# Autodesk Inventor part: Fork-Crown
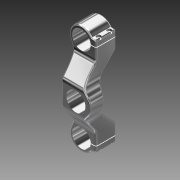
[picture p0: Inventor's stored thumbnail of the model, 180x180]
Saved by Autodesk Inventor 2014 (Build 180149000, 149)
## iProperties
Shininess: 64.0
Length Units: 11272
Angle Units: 11279
Time Units: 11290
Mass Units: 11286
Length Display Precision: 3
Angle Display Precision: 2
Compacted: True
Created: 2001-11
Part Number: Fork-Crown
Document SubType Name: Modeling
Designer: Autodesk, Inc.
Mass: 96.1049 g
Surface Area: 286.05 cm^2
Volume: 96.1049 cm^3
Density: 1 g/cm^3
Material: Generic
Appearance: Chrome - Polished
Density: 0.0
Volumn: 0.0
Area: 0.0
PropertySet Name: Model Information
Control State: 0
Master: False
Checked Out: False
Author: Autodesk, Inc.
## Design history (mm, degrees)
sketch "Sketch1"
  geometry: L1 (387.107, 198.738)-(394.972, 198.738); L2 (387.081, 199.805)-(394.972, 199.805); L3 (394.972, 205.703)-(394.972, 199.805); L4 (390.064, 208.878)-(391.797, 208.878); L5 (362.993, 135.224)-(362.993, 160.563); L6 (394.972, 198.738)-(394.972, 166.433); L7 (362.993, 135.224)-(406.863, 135.224); L8 (362.993, 135.224)-(362.993, 109.884); L9 (387.081, 70.642)-(394.972, 70.642); L10 (394.972, 64.744)-(394.972, 70.642); L11 (390.064, 61.569)-(391.797, 61.569); L12 (387.107, 71.709)-(394.972, 71.709); L13 (394.972, 71.709)-(394.972, 104.014); A1 r 13.97 centre (373.138, 198.936) between (387.081, 199.805) and (387.107, 198.738); A2 r 3.175 centre (391.797, 205.703) between (394.972, 205.703) and (391.797, 208.878); A3 r 3.048 centre (390.064, 211.926) between (387.646, 210.07) and (390.064, 208.878); A4 r 18.288 centre (373.138, 198.936) between (387.646, 210.07) and (356.426, 191.509); A5 r 76.2 centre (286.793, 160.563) between (362.993, 160.563) and (356.426, 191.509); A6 r 25.4 centre (420.372, 166.433) between (394.972, 166.433) and (401.412, 149.532); A7 r 21.504 centre (385.359, 135.224) between (406.863, 135.224) and (401.412, 149.532); A8 r 76.2 centre (286.793, 109.884) between (356.426, 78.938) and (362.993, 109.884); A9 r 18.288 centre (373.138, 71.511) between (356.426, 78.938) and (387.646, 60.377); A10 r 3.175 centre (391.797, 64.744) between (391.797, 61.569) and (394.972, 64.744); A11 r 3.048 centre (390.064, 58.521) between (390.064, 61.569) and (387.646, 60.377); A12 r 13.97 centre (373.138, 71.511) between (387.107, 71.709) and (387.081, 70.642); A13 r 25.4 centre (420.372, 104.014) between (401.412, 120.915) and (394.972, 104.014); A14 r 21.504 centre (385.359, 135.224) between (401.412, 120.915) and (406.863, 135.224)
  constraints: 28 point on circle, 26 end point, 18 symmetric about line, 14 centre point, 8 tangent, 3 horizontal, 3 vertical, 1 collinear, 1 concentric, 1 horizontal alignment, 1 perpendicular, 15 other
  dimensions: "d1" = 13.97 radius of A1; "d7" = 76.2 radius of A5; "d9" = 18.288 radius of A4; "d92" = 3.175 radius of A2; "d94" = 5.89767 distance from line of A2.centre L2; "d95" = 1.06735 distance between parallel lines of L2 L1; "d99" = 12.2212 horizontal distance of A7.centre A1.centre; "d100" = 25.4 radius of A6; "d101" = 21.50376 radius of A7; "d102" = 3.048 radius of A3; "d103" = 25.33944 distance of L5.start L5.end; "d104" = 43.87007 distance of L5.start L7.end
extrude "ExtrusionBlind1" new body sketch "Sketch1" distance "d16" = 76.2; taper "d17" = 0 deg
node "WorkPlane1"
workaxis "Work Axis4"
sketch "Sketch9"
  geometry: L1 (28.214, 35.429)-(47.471, 16.806); L2 (47.471, 16.806)-(82.009, 16.806); L3 (82.009, 47.286)-(45.305, 47.286); L4 (45.305, 47.286)-(19.099, 67.761); L5 (19.099, 67.761)-(0.009, 67.761); L6 (0.009, 45.941)-(0.009, 67.761); L7 (0.009, -15.24)-(0.009, 91.44) reference; L8 (25.348, 76.2)-(-25.331, 76.2) reference; L9 (82.009, 0)-(82.009, 76.2) reference; L10 (-25.331, 0)-(25.348, 0) reference; L11 (-28.197, 35.429)-(-47.454, 16.806); L12 (-45.288, 47.286)-(-19.081, 67.761); L13 (-19.081, 67.761)-(0.009, 67.761); L14 (0.009, 45.941)-(0.009, 67.761); L15 (-81.992, 47.286)-(-45.288, 47.286); L16 (-47.454, 16.806)-(-81.992, 16.806); L17 (-81.992, 0)-(-81.992, 76.2) reference; A1 r 37.592 centre (2.081, 8.406) between (28.214, 35.429) and (0.009, 45.941); A2 r 37.592 centre (-2.064, 8.406) between (0.009, 45.941) and (-28.197, 35.429)
  constraints: 24 end point, 5 point on line, 5 symmetric about line, 4 point on circle, 3 horizontal, 2 centre point, 1 tangent, 1 vertical, 7 other
  dimensions: "d26" = 30.48 vertical distance of L1.end L3.end; "d30" = 37.592 radius of A1; "d105" = 8.43916 distance between parallel lines of L5 L8; "d106" = 8.40601 distance from line of L10 A1.centre; "d108" = 142 deg angle of L4 L5; "d109" = 19.09001 distance of L4.end L5.end; "d110" = 20.47486 distance between parallel lines of L5 L3; "d111" = 135.959 deg angle of L2 L1
extrude "ExtrusionThru1" sketch "Sketch9" stored distance "d35" = 3.302; taper "d36" = 0 deg
fillet "Fillet1" dims "d38" = 12.7
fillet "Fillet3" dims "d73" = 6.35
sketch "Sketch15"
  geometry: L1 (6.35, -28.694)-(6.35, -5.08); L2 (6.35, -5.08)-(29.21, -5.08); L3 (0, 16.052)-(0, 0) reference; L4 (35.262, 0)-(0, 0) reference; A1 r 19.05 centre (9.613, -47.462) between (22.86, -33.772) and (6.35, -28.694); A2 r 76.2 centre (99.038, -35.583) between (29.21, -5.08) and (22.86, -33.772); A3 r 21.504 centre (9.613, -47.462) between (-6.439, -33.154) and (-6.439, -61.771) reference; 3 further points
  constraints: 4 end point, 4 point on circle, 2 centre point, 1 coincident, 1 perpendicular, 2 other
  dimensions: "d113" = 6.35 distance between parallel lines of L1 L3; "d114" = 5.08 distance between parallel lines of L4 L2; "d115" = 76.2 radius of A2; "d116" = 22.86 distance of L1.end L2.end; "d117" = 19.05 radius of A1; "d118" = 6.35 horizontal distance of A1.start L2.end
extrude "Extrusion4" cut sketch "Sketch15" distance "d75" = 25.4; taper "d76" = 0 deg
fillet "Fillet5" dims "d77" = 5.08
workplane "Work Plane5"
mirror "Mirror1"
sketch "Sketch16"
  geometry: L1 (-22.366, 14.717)-(15.696, 14.717) reference; L2 (-22.366, 14.717)-(-22.366, -14.717) reference; L3 (15.696, -14.717)-(-22.366, -14.717) reference; A1 r 25.4 centre (35.013, -31.21) between (16.052, -14.309) and (15.696, -14.717) reference; A2 r 21.504 centre (0, 0) between (16.052, -14.309) and (16.052, 14.309) reference; A3 r 25.4 centre (35.013, 31.21) between (15.696, 14.717) and (16.052, 14.309) reference
hole "Hole6" sketch "Sketch16" at (0, 0) diameter "d80" = 28.575; stored, may be unused: countersink angle "d84" = 82 deg, drill point angle "d86" = 118 deg; dims "d81" = 12.7, "d82" = 9.525, "d83" = 6.35, "d85" = 19.05
fillet "Fillet6" dims "d120" = 2.54
workplane "Work Plane6"
sketch "Sketch18"
  geometry: L1 (-21.834, 19.346)-(-21.834, 44.746) reference; 2 further points
  constraints: 1 vertical alignment
  dimensions: "d121" = 15.875 distance of point (-18.659, 24.052) point (-18.659, 39.927); "d129" = 3.175 distance from line of point (-18.659, 39.927) L1
hole "Hole7" sketch "Sketch18" at (-18.659, 39.927), (-18.659, 24.052) diameter "d122" = 3.2512; stored, may be unused: countersink angle "d126" = 82 deg, drill point angle "d128" = 118 deg; dims "d123" = 12.7, "d124" = 6.35, "d125" = 11.43, "d127" = 25.4
mirror "Mirror2"
body "Solid1"
node "Projected Loop1"
other parameters: "mdtd132" = 1.3 [user parameter], "mdtd133" = 3.8 [user parameter], "mdtd136" = 1 [user parameter], "d0" = 14.732 (derived), "d2" = 127 (derived), "d4" = 20.574 (derived), "d6" = 76.2 (derived), "d8" = 18.288 (derived), "d10" = 1.016 (derived), "d12" = 25.4 (derived), "d14" = 23.622 (derived), "d18" = 0, "d19" = 0, "d20" = 0, "d21" = 0, "d22" = 0, "d23" = 0, "d25" = 30.48 (derived), "d27" = 38.354 (derived), "d29" = 37.592 (derived), "d31" = 50.8 (derived), "d33" = 142 deg (derived), "d37" = 0, "d39" = 0, "Hole" = 28.575 [user parameter], "d119" = 0
